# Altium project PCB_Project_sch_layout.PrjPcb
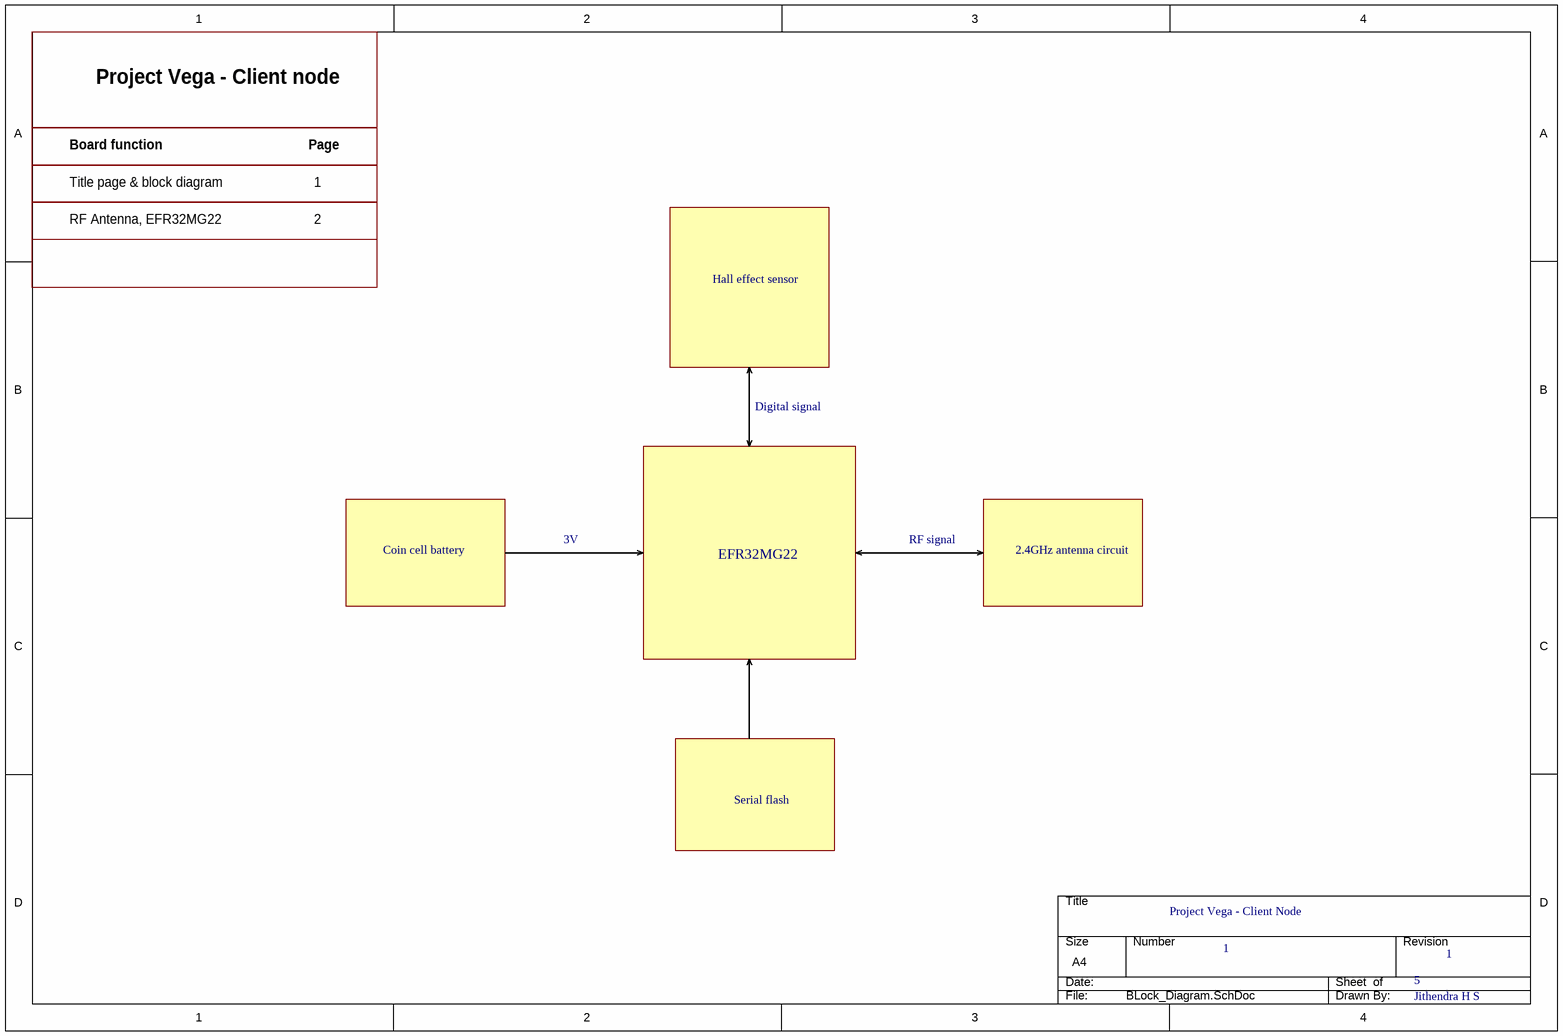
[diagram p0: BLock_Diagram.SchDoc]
5 sheets, 120 parts. Net scope: flat (ports and power ports of the same name join across sheets).
Sheets:
  BLock_Diagram.SchDoc
  Principal.SchDoc
  Power_Sheet.SchDoc
  Project_Vega_Sensors_Schematic.SchDoc
  Client_Node.SchDoc

## Sheet BLock_Diagram.SchDoc: Project Vega - Client Node
size A4; DrawnBy: Jithendra H S; Revision: 1; SheetNumber: 1; SheetTotal: 5

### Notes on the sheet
- Project Vega - Client node
- Board function
- Page
- Title page & block diagram
- RF Antenna, EFR32MG22
- 1
- 2
- Hall effect sensor
- Digital signal
- Coin cell battery
- 3V
- EFR32MG22
- RF signal
- 2.4GHz antenna circuit
- Serial flash

## Sheet Principal.SchDoc
size A4; SheetNumber: 1; SheetTotal: 5
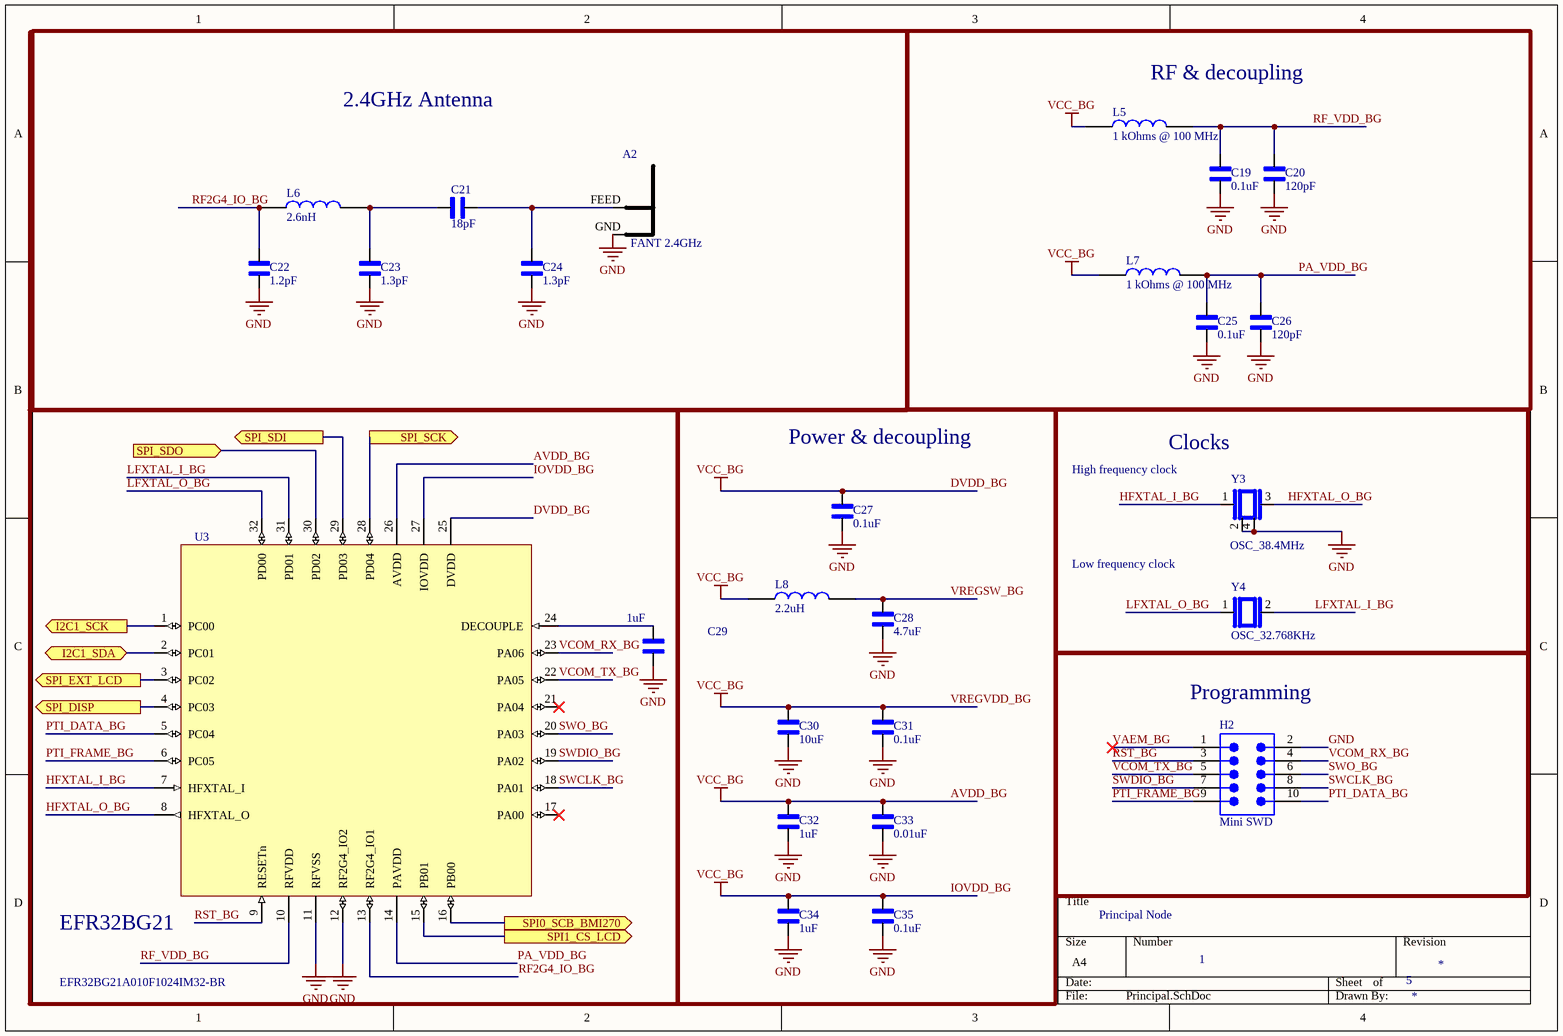
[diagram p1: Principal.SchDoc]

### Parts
A2  FANT 2.4GHz  [FANT_2P4]
C19  0.1uF  [CAPC1608X90]
C20  120pF  [CAPC1608X90]
C21  18pF  [CAPC1608X90]
C22  1.2pF  [CAPC1608X90]
C23  1.3pF  [CAPC1608X90]
C24  1.3pF  [CAPC1608X90]
C25  0.1uF  [CAPC1608X90]
C26  120pF  [CAPC1608X90]
C27  0.1uF  [CAPC1608X90]
C28  4.7uF  [CAPC1608X90]
C29  1uF  [CAPC1608X90]
C30  10uF  [CAPC1608X90]
C31  0.1uF  [CAPC1608X90]
C32  1uF  [CAPC1608X90]
C33  0.01uF  [CAPC1608X90]
C34  1uF  [CAPC1608X90]
C35  0.1uF  [CAPC1608X90]
H2  Mini SWD  [FTSH-105-01-XXX-DV-K]
L5  1 kOhms @ 100 MHz  [INDC1608X95N]
L6  2.6nH  [INDC1608X95N]
L7  1 kOhms @ 100 MHz  [INDC1608X95N]
L8  2.2uH  [INDC1608X95N]
U3  EFR32BG21A010F1024IM32-BR  [QFN32-EFR32xG2xIM32-BR]
Y3  OSC_38.4MHz  [OSC_38.4MHz]
Y4  OSC_32.768KHz  [OSC_32.768KHz]

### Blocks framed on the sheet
2.4GHz Antenna: A2 C21-C24 L6
RF & decoupling: C19 C20 C25 C26 L5 L7
EFR32BG21: C29 U3
Power & decoupling: C27 C28 C30-C35 L8
Clocks: Y3 Y4
Programming: H2

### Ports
I2C1_SCK (out, see Project_Vega_Sensors_Schematic[3A], Project_Vega_Sensors_Schematic[3C]), I2C1_SDA (bidir, see Project_Vega_Sensors_Schematic[3A], Project_Vega_Sensors_Schematic[3C]), SPI0_SCB_BMI270 (out, see Project_Vega_Sensors_Schematic[1A]), SPI1_CS_LCD (out, see Project_Vega_Sensors_Schematic[1C]), SPI_DISP (out, see Project_Vega_Sensors_Schematic[1C]), SPI_EXT_LCD (out, see Project_Vega_Sensors_Schematic[1C]), SPI_SCK (out, see Project_Vega_Sensors_Schematic[1A], Project_Vega_Sensors_Schematic[1C]), SPI_SDI (out, see Project_Vega_Sensors_Schematic[1A], Project_Vega_Sensors_Schematic[1C]), SPI_SDO (in, see Project_Vega_Sensors_Schematic[1A])

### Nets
AVDD_BG: C27.1 C30.1 C31.1 C32.1 C33.1 C34.1 C35.1 L5.1 L7.1 L8.1 U3.25(DVDD) U3.26(AVDD) U3.27(IOVDD)  [also labelled DVDD_BG, IOVDD_BG, VCC_BG, VREGVDD_BG]
GND: A2.GND C19.2 C20.2 C22.2 C23.2 C24.2 C25.2 C26.2 C27.2 C28.2 C29.2 C30.2 C31.2 C32.2 C33.2 C34.2 C35.2 H2.2 U3.11(RFVSS) U3.12(RF2G4_IO2) Y3.2 Y3.4
HFXTAL_I_BG: U3.7(HFXTAL_I) Y3.1
HFXTAL_O_BG: U3.8(HFXTAL_O) Y3.3
LFXTAL_I_BG: U3.31(PD01) Y4.2
LFXTAL_O_BG: U3.32(PD00) Y4.1
PA_VDD_BG: C25.1 C26.1 L7.2 U3.14(PAVDD)
PTI_DATA_BG: H2.10 U3.5(PC04)
PTI_FRAME_BG: H2.9 U3.6(PC05)
RF2G4_IO_BG: C22.1 L6.1 U3.13(RF2G4_IO1)
RF_VDD_BG: C19.1 C20.1 L5.2 U3.10(RFVDD)
RST_BG: H2.3 U3.9(RESETn)
SWCLK_BG: H2.8 U3.18(PA01)
SWDIO_BG: H2.7 U3.19(PA02)
SWO_BG: H2.6 U3.20(PA03)
VAEM_BG: H2.1
VCOM_RX_BG: H2.4 U3.23(PA06)
VCOM_TX_BG: H2.5 U3.22(PA05)
VREGSW_BG: C28.1 L8.2
NetA2_FEED: A2.FEED C21.2 C24.1
NetC21_1: C21.1 C23.1 L6.2
NetC29_1: C29.1 U3.24(DECOUPLE)
NetC?#6_2: U3.4(PC03) ; port SPI_DISP
NetP?_1: U3.28(PD04) ; port SPI_SCK
NetP?_2: U3.29(PD03) ; port SPI_SDI
NetP?_3: U3.15(PB01) ; port SPI1_CS_LCD
NetP?_4: U3.3(PC02) ; port SPI_EXT_LCD
NetR?#2_1: U3.2(PC01) ; port I2C1_SDA
NetR?#3_1: U3.1(PC00) ; port I2C1_SCK
NetU3_16: U3.16(PB00) ; port SPI0_SCB_BMI270
NetU3_30: U3.30(PD02) ; port SPI_SDO

Not connected (* = marked no-connect by the designer): U3 17(PA00)* 21(PA04)*

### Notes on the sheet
- (near Y3) High frequency clock
- Low frequency clock
- Principal Node

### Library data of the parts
A2 = FANT_2P4: Inverted F antenna
C19-C35 = CC0603KRX7R9BB104: 0.1 ÂµF Â±10% 50V Ceramic Capacitor X7R 0603 (1608 Metric); MF: Yageo
H2 = Debug Connector Mini SWD - 0.05": Mini SWD 0.05" Pitch Connector - 10 Pin SMT Box Header; Manufacturer: Adafruit Industries; Manufacturer Part Number: 4048
L5-L8 = LQM18DN100M70L: Inductor with Inductance 10uH Tol.+/-20% Package 0603 (1608); MF: Murata Electronics
U3 = EFR32BG21A010F1024IM32-BR: Blue Gecko, QFN32, 2.4G, 10dB, Bluetooth 5.1, 1024kB, 96kB(RAM), 20 GPIO; Manufacturer: Silicon Labs
Y3 = OSC_38.4MHz: 38.4 MHz ±10ppm Crystal 10pF 40 Ohms 4-SMD, No Lead; MF: {'manufacturer': u'Murata Electronics'}; MP: XRCGB38M400F2P00R0
Y4 = OSC_32.768KHz: Tuning Fork Crystal 32.768kHz in 1.2 x 2.0mm package; MF: Micro Crystal; MP: CM8V-T1A-32.768KHZ-7PF-20PPM-TA-QC

## Sheet Power_Sheet.SchDoc
size A4; SheetNumber: 2; SheetTotal: 5
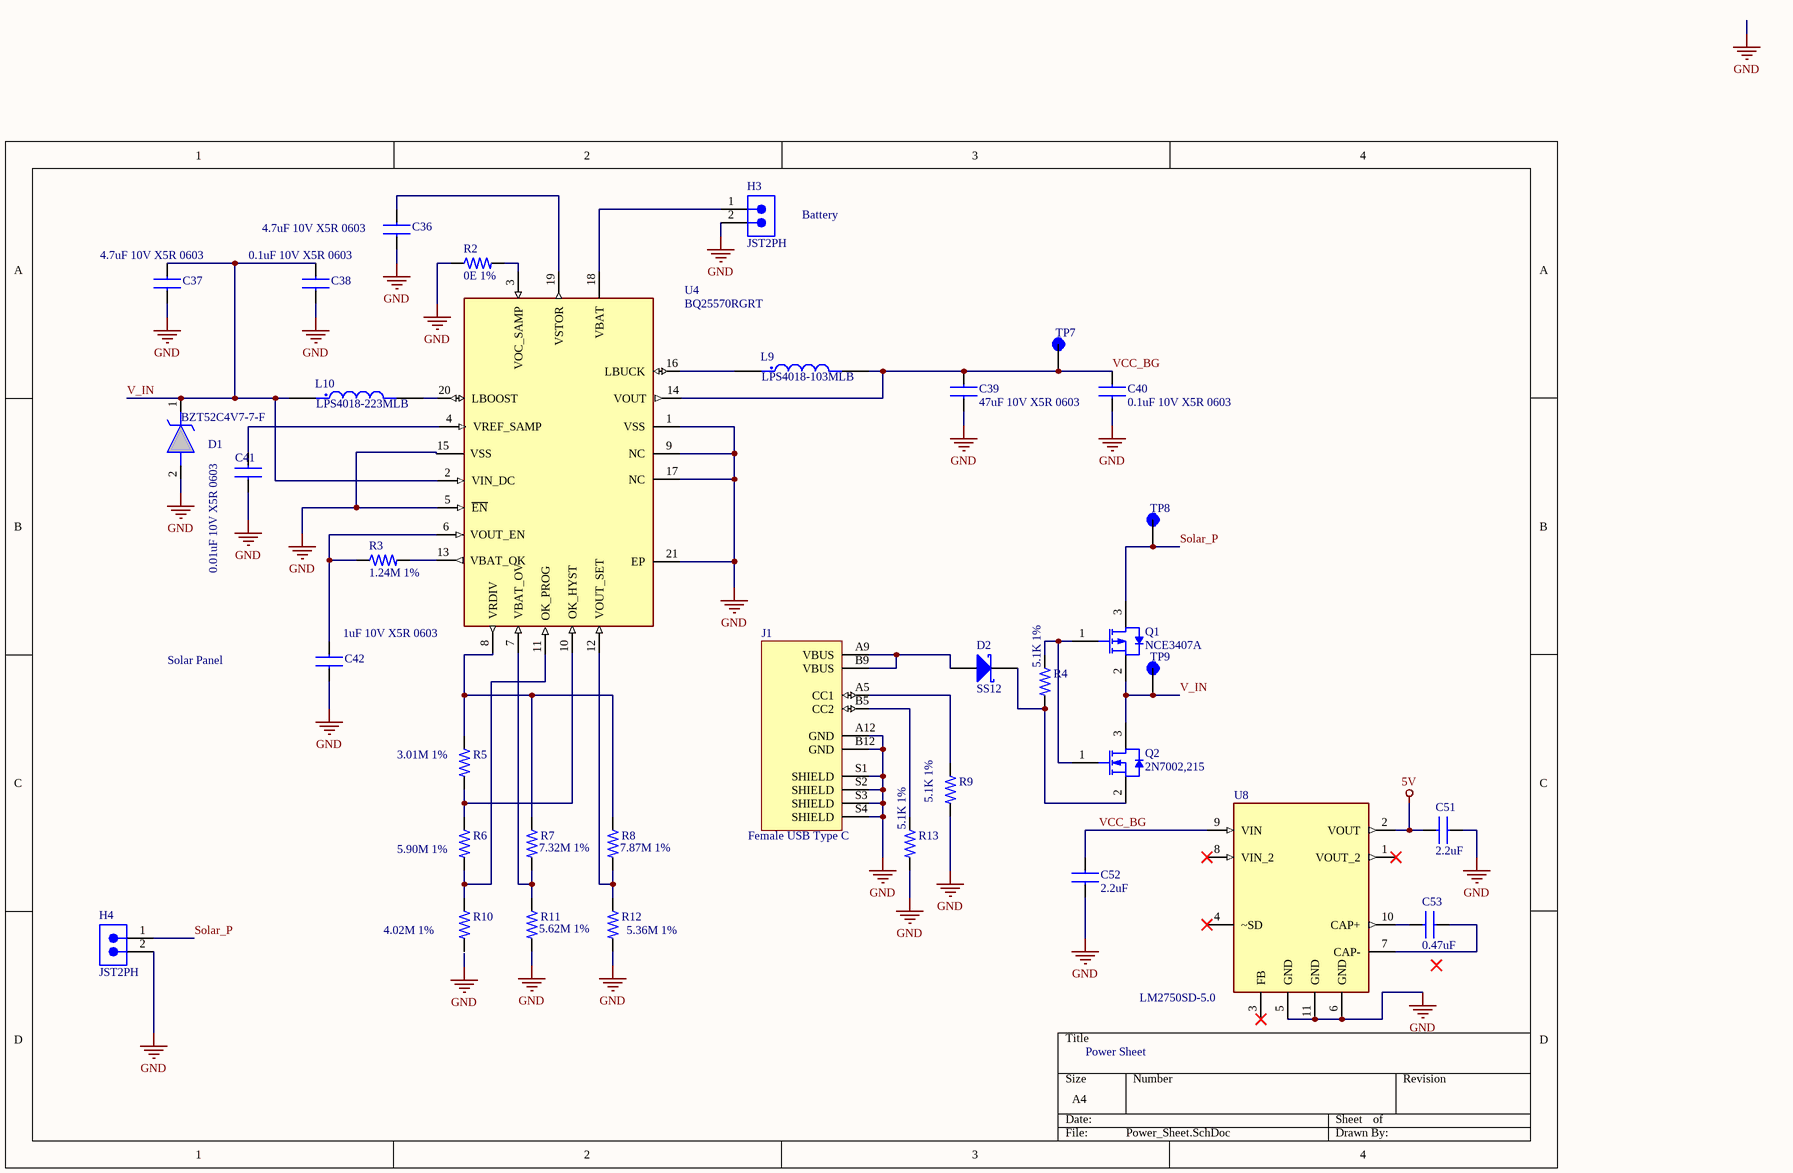
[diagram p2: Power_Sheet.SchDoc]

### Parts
C36  4.7uF 10V X5R 0603  [CAP_0603_1MM]
C37  4.7uF 10V X5R 0603  [CAP_0603_1MM]
C38  0.1uF 10V X5R 0603  [CAP_0603_1MM]
C39  47uF 10V X5R 0603  [CAP_0603_1MM]
C40  0.1uF 10V X5R 0603  [CAP_0603_1MM]
C41  0.01uF 10V X5R 0603  [CAP_0603_1MM]
C42  1uF 10V X5R 0603  [CAP_0603_1MM]
C51  2.2uF  [CAP_0603_1MM]
C52  2.2uF  [CAP_0603_1MM]
C53  0.47uF  [CAP_0603_1MM]
D1  BZT52C4V7-7-F  [SOD3716X145N]
D2  SS12  [FAIR-DO-214AC-2_V]
H3  JST2PH  [JST_B2B-PH-K-S(LF)(SN)]
H4  JST2PH  [JST_B2B-PH-K-S(LF)(SN)]
J1  Female USB Type C  [GCT_USB4125-GF-A_REVA2]
L9  LPS4018-103MLB  [IND_LPS4018-223MRC]
L10  LPS4018-223MLB  [IND_LPS4018-223MRC]
Q1  NCE3407A  [NCEP-SOT23-3_M]
Q2  2N7002,215  [NXP-SOT23-3_V]
R2  0E 1%  [RES_0603_1608X06]
R3  1.24M 1%  [RES_0603_1608X06]
R4  5.1K 1%  [RES_0603_1608X06]
R5  3.01M 1%  [RES_0603_1608X06]
R6  5.90M 1%  [RES_0603_1608X06]
R7  7.32M 1%  [RES_0603_1608X06]
R8  7.87M 1%  [RES_0603_1608X06]
R9  5.1K 1%  [RES_0603_1608X06]
R10  4.02M 1%  [RES_0603_1608X06]
R11  5.62M 1%  [RES_0603_1608X06]
R12  5.36M 1%  [RES_0603_1608X06]
R13  5.1K 1%  [RES_0603_1608X06]
TP7  Test_point  [TP]  (value not drawn)
TP8  Test_point  [TP]  (value not drawn)
TP9  Test_point  [TP]  (value not drawn)
U4  BQ25570RGRT  [QFN50P350X350X100-21N]
U8  LM2750SD-5.0  [LM2750_DFN300X300X80-11N]

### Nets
5V: C51.2 U8.2(VOUT)
GND: C36.1 C37.1 C38.1 C39.1 C40.1 C41.1 C42.1 C51.1 C52.1 D1.2(A) H3.2 H4.2 J1.A12(GND) J1.B12(GND) J1.S1(SHIELD) J1.S2(SHIELD) J1.S3(SHIELD) J1.S4(SHIELD) R2.1 R9.2 R11.2 R12.2 R13.2 U4.1(VSS) U4.5(~{EN}) U4.9(NC) U4.15(VSS) U4.17(NC) U4.21(EP) U8.5(GND) U8.6(GND) U8.11(GND)
Solar_P: H4.1 Q1.3(DRAIN) TP8.TP
V_IN: C37.2 C38.2 D1.1(K) L10.1 Q1.2(SOURCE) Q2.3(D) TP9.TP U4.2(VIN_DC)
VCC_BG: C39.2 C40.2 C52.2 L9.2 TP7.TP U4.14(VOUT) U8.9(VIN)
NetC36_2: C36.2 U4.19(VSTOR)
NetC41_2: C41.2 U4.4(VREF_SAMP)
NetC42_2: C42.2 R3.1 U4.6(VOUT_EN)
NetC53_1: C53.1 U8.7(CAP-)
NetC53_2: C53.2 U8.10(CAP+)
NetD2_1: D2.1(A) J1.A9(VBUS) J1.B9(VBUS)
NetD2_2: D2.2(K) Q2.2(S) R4.2
NetH3_1: H3.1 U4.18(VBAT)
NetJ1_A5: J1.A5(CC1) R9.1
NetJ1_B5: J1.B5(CC2) R13.1
NetL9_1: L9.1 U4.16(LBUCK)
NetL10_2: L10.2 U4.20(LBOOST)
NetQ1_1: Q1.1(GATE) Q2.1(G) R4.1
NetR2_2: R2.2 U4.3(VOC_SAMP)
NetR3_2: R3.2 U4.13(VBAT_OK)
NetR5_1: R5.1 R7.1 R8.1 U4.8(VRDIV)
NetR5_2: R5.2 R6.1 U4.10(OK_HYST)
NetR6_2: R6.2 R10.1 U4.11(OK_PROG)
NetR7_2: R7.2 R11.1 U4.7(VBAT_OV)
NetR8_2: R8.2 R12.1 U4.12(VOUT_SET)

Not connected (* = marked no-connect by the designer): R10 2; U8 1(VOUT_2)* 3(FB)* 4(~SD)* 8(VIN_2)*

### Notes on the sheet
- Battery
- Solar Panel
- Power Sheet

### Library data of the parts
C36-C42 C52 C53 = GRM188R61A226ME15D: CAP CER 22UF 10V X5R 0603; Manufacturer: Murata; Voltage Rating DC: 10 VDC; Tolerance: 20 %; Brand: Murata Electronics; Type: Voltage and Temperature Derating Recommended Product; Unit Weight: 0.000222 oz
C51 = GRM188R61A226ME15D: Manufacturer: Murata; Capacitance: 22 uF; Voltage Rating DC: 10 VDC; Dielectric: X5R; Tolerance: 20 %; Brand: Murata Electronics; Type: Voltage and Temperature Derating Recommended Product; Unit Weight: 0.000222 oz
D1 = BZT52C4V7-7-F: Diodes Inc BZT52C4V7-7-F Zener Diode, 4.7V 7% 500 mW SMT 2-Pin SOD-123; Manufacturer_Name: Diodes Incorporated; Geometry.Height: 1.45mm
D2 = CMP-004-00016-2: Schottky Rectifier, 20 V, 1 A, -65 to 125 degC, 2-Pin DO-214AC, RoHS, Tape and Reel; Manufacturer: Fairchild; Forward Voltage: 500mV; Peak Reverse Current: 200uA; Max Surge Current: 40A
H3 H4 = JST2PH: Connector Header Through Hole 2 position 0.079" (2.00mm); Manufacturer: JST; Manufacturer Part Number: B2B-PH-K-S
J1 = USB-C Power Connector: USB-C (USB TYPE-C) Receptacle Connector 24 (6+18 Dummy) Position Surface Mount, Right Angle; Through Hole; Manufacturer Part Number: USB4125-GF-A_REVA2
L9 L10 = LPS4018-223MRC: 22 µH Shielded Drum Core Inductor 650 mA 360mOhm Max Nonstandard; MF: Coilcraft
Q1 = CMP-013-00018-3: P-Channel Enhancement Mode Power MOSFET, 30 V, 4.3 A, - 55 to 150 degC, 3-Pin SOT23, RoHS, Tape and Reel; Manufacturer: NCE Power
Q2 = CMP-013-00011-4: N-channel Trench MOSFET, 60 V, 300 mA, -65 to 150 degC, 3-Pin SOT-23 (TO-236AB), RoHS, Tape and Reel; Manufacturer: NXP Semiconductors; Elements: 1; Power: 830mW; Max Dual Supply Voltage: 60V; Rds On Max: 5Ohm; Package Version: Feb-16; Nominal Vgs: 2V; Input Capacitance: 50pF
R2 R3 R5-R12 = RC0603FR-07316KL: SMD Chip Resistor, 316 kOhm, ± 1%, 100 mW, 0603 [1608 Metric], Thick Film, General Purpose; Manufacturer: Yageo; Value: 316kR; Power Rating: 100mW; Voltage Rating: 50V; Temperature Coefficient: 100ppm/°C
R4 R13 = RC0603FR-07316KL: SMD Chip Resistor, 5.1KOhm, ± 1%, 100 mW, 0603 [1608 Metric], Thick Film, General Purpose; Manufacturer: Yageo; Value: 316kR; Power Rating: 100mW; Voltage Rating: 50V; Temperature Coefficient: 100ppm/°C
TP7-TP9 = Test_point: SMT Test Point- Mininature-1000 pc Reels; MP: 5019; MF: Keystone Electronics
U4 = BQ25570RGRT: Ultra Low power Harvester power Management IC with boost charger, and Nanopower Buck Converter 20-VQFN -40 to 125; MF: Texas Instruments
U8 = LM2750SD-5.0: IC CONV REG SW CAP 5V; MP: LM2750SD-5-0

## Sheet Project_Vega_Sensors_Schematic.SchDoc: Principal Node_Sensor Schematic
size A; Date: 10/08/2024; Author: Prudhvi Kondapalli; CompanyName: CU Boulder; Engineer: Prudhvi Kondapalli; DocumentNumber: 1; Revision: 1; SheetNumber: 5; SheetTotal: 5
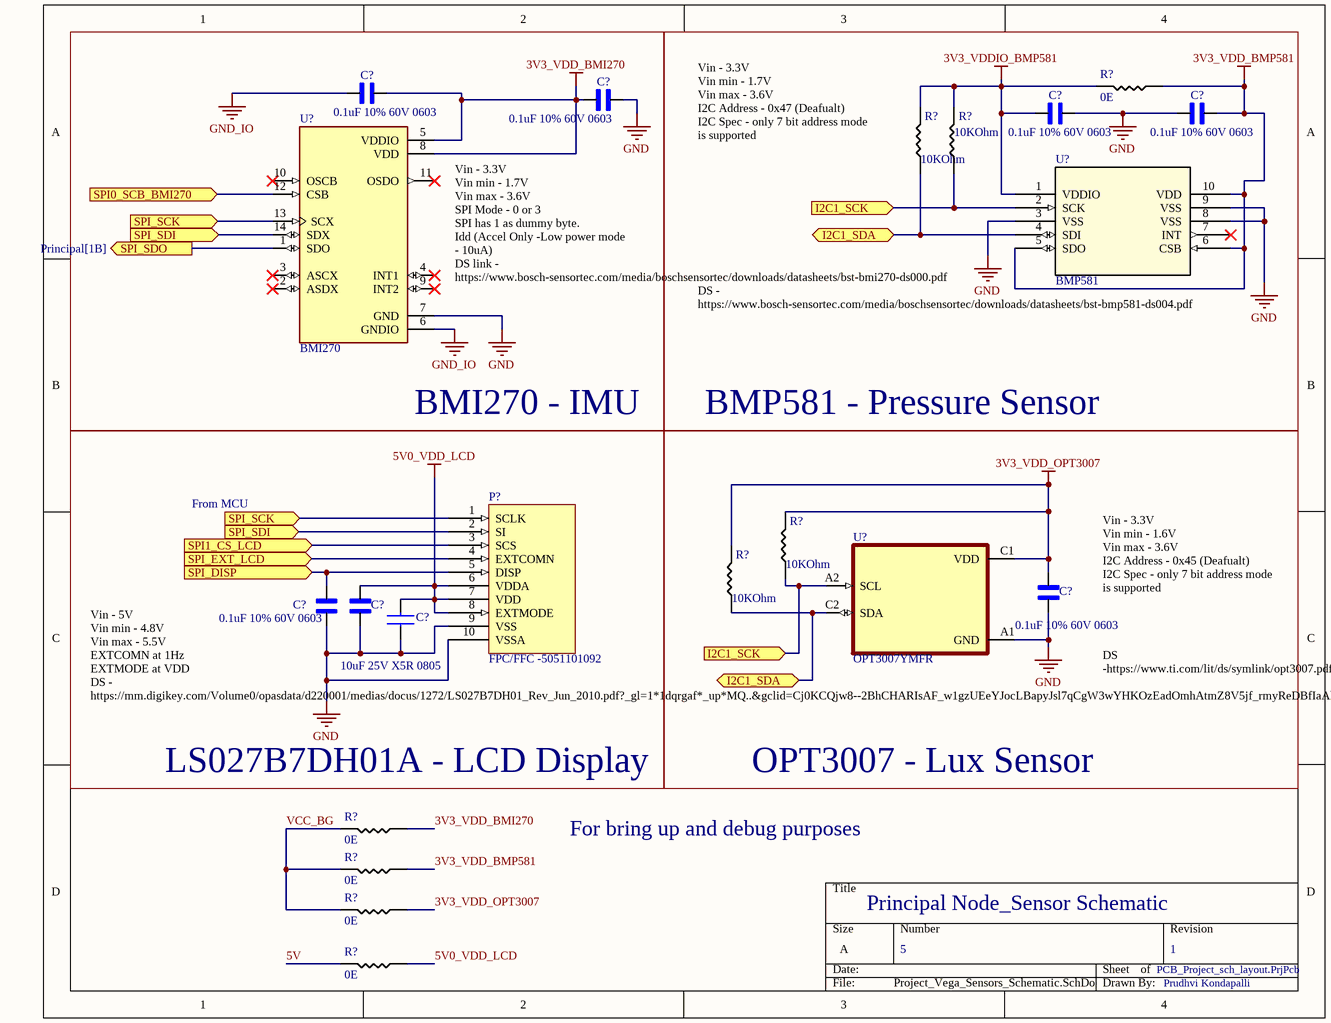
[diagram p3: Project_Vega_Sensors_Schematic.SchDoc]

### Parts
(Parts that share a designator on the sheet are numbered #1, #2 ... from top to bottom, then left to right.)
C?#1  0.1uF 10% 60V 0603  [CAPC1608X90]
C?#2  0.1uF 10% 60V 0603  [CAPC1608X90]
C?#3  0.1uF 10% 60V 0603  [CAPC1608X90]
C?#4  0.1uF 10% 60V 0603  [CAPC1608X90]
C?#5  0.1uF 10% 60V 0603  [CAPC1608X90]
C?#6  0.1uF 10% 60V 0603  [CAPC1608X90]
C?#7  0.1uF 10% 60V 0603  [CAPC1608X90]  (value not drawn)
C?#8  10uF 25V X5R 0805  [CAP_0805_2mmX1.25mm]
P?  FPC/FFC -5051101092  [CON_5051101092_MOL]
R?#1  value 0E  [1206_Passive_Resitor]  (hidden comment: 10k)
R?#2  value 10KOhm  [1206_Passive_Resitor]  (hidden comment: 10k)
R?#3  value 10KOhm  [1206_Passive_Resitor]  (hidden comment: 10k)
R?#4  value 10KOhm  [1206_Passive_Resitor]  (hidden comment: 10k)
R?#5  value 10KOhm  [1206_Passive_Resitor]  (hidden comment: 10k)
R?#6  value 0E  [1206_Passive_Resitor]  (hidden comment: 10k)
R?#7  value 0E  [1206_Passive_Resitor]  (hidden comment: 10k)
R?#8  value 0E  [1206_Passive_Resitor]  (hidden comment: 10k)
R?#9  value 0E  [1206_Passive_Resitor]  (hidden comment: 10k)
U?#1  BMP581  [QFN10_BMP581_BOS-M]
U?#2  BMI270  [XDCR_BMI270]
U?#3  OPT3007YMFR  [BGA6N60X35P2X3_85X94X22N]

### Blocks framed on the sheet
BMI270 - IMU: C?#1 C?#2 U?#2
BMP581 - Pressure Sensor: C?#3 C?#4 R?#1-R?#3 U?#1

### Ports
I2C1_SCK (in, see Principal[1C], Project_Vega_Sensors_Schematic[3A]), I2C1_SCK (in, see Principal[1C], Project_Vega_Sensors_Schematic[3C]), I2C1_SDA (bidir, see Principal[1C], Project_Vega_Sensors_Schematic[3A]), I2C1_SDA (bidir, see Principal[1C], Project_Vega_Sensors_Schematic[3C]), SPI0_SCB_BMI270 (in, see Principal[2D]), SPI1_CS_LCD (in, see Principal[2D]), SPI_DISP (in, see Principal[1C]), SPI_EXT_LCD (in, see Principal[1C]), SPI_SCK (in, see Principal[1B], Project_Vega_Sensors_Schematic[1A]), SPI_SCK (in, see Principal[1B], Project_Vega_Sensors_Schematic[1C]), SPI_SDI (in, see Principal[1B], Project_Vega_Sensors_Schematic[1A]), SPI_SDI (in, see Principal[1B], Project_Vega_Sensors_Schematic[1C]), SPI_SDO (out, see Principal[1B])

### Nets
3V3_VDD_BMI270: C?#1.2 C?#2.1 R?#6.1 U?#2.5(VDDIO) U?#2.8(VDD)
3V3_VDD_BMP581: C?#4.2 R?#1.1 R?#7.1 U?#1.5(SDO) U?#1.6(CSB) U?#1.10(VDD)
3V3_VDD_OPT3007: C?#5.2 R?#4.2 R?#5.2 R?#8.1 U?#3.C1(VDD)
3V3_VDDIO_BMP581: C?#3.1 R?#1.2 R?#2.2 R?#3.2 U?#1.1(VDDIO)
5V0_VDD_LCD: C?#7.2 C?#8.1 P?.6(VDDA) P?.7(VDD) P?.8(EXTMODE) R?#9.1
GND: C?#2.2 C?#3.2 C?#4.1 C?#5.1 C?#6.1 C?#7.1 C?#8.2 P?.9(VSS) P?.10(VSSA) U?#1.3(VSS) U?#1.8(VSS) U?#1.9(VSS) U?#2.7(GND) U?#3.A1(GND)
GND_IO: C?#1.1 U?#2.6(GNDIO)
5V: R?#9.2
VCC_BG: R?#6.2 R?#7.2 R?#8.2
NetC?#6_2: C?#6.2 P?.5(DISP) ; port SPI_DISP
NetP?_1: P?.1(SCLK) U?#2.13(SCX) ; port SPI_SCK
NetP?_2: P?.2(SI) U?#2.14(SDX) ; port SPI_SDI
NetP?_3: P?.3(SCS) ; port SPI1_CS_LCD
NetP?_4: P?.4(EXTCOMN) ; port SPI_EXT_LCD
NetR?#2_1: R?#2.1 R?#5.1 U?#1.4(SDI) U?#3.C2(SDA) ; port I2C1_SDA
NetR?#3_1: R?#3.1 R?#4.1 U?#1.2(SCK) U?#3.A2(SCL) ; port I2C1_SCK
NetU3_16: U?#2.12(CSB) ; port SPI0_SCB_BMI270
NetU3_30: U?#2.1(SDO) ; port SPI_SDO

Not connected (* = marked no-connect by the designer): U?#1 7(INT)*; U?#2 2(ASDX)* 3(ASCX)* 4(INT1)* 9(INT2)* 10(OSCB)* 11(OSDO)*

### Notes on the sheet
- (near R?#2) Vin - 3.3V
  Vin min - 1.7V
  Vin max - 3.6V
  I2C Address - 0x47 (Deafualt)
  I2C Spec - only 7 bit address mode is supported
- Vin - 3.3V
  Vin min - 1.7V
  Vin max - 3.6V
  SPI Mode - 0 or 3
  SPI has 1 as dummy byte.
  Idd (Accel Only -Low power mode - 10uA)
  DS link - https://www.bosch-sensortec.com/media/boschsensortec/downloads/datasheets/bst-bmi270-ds000.pdf
- DS - https://www.bosch-sensortec.com/media/boschsensortec/downloads/datasheets/bst-bmp581-ds004.pdf
- From MCU
- Vin - 3.3V
  Vin min - 1.6V
  Vin max - 3.6V
  I2C Address - 0x45 (Deafualt)
  I2C Spec - only 7 bit address mode is supported
- DS -https://www.ti.com/lit/ds/symlink/opt3007.pdf?HQS=dis-dk-null-digikeymode-dsf-pf-null-wwe&ts=1728281957104&ref_url=https%253A%252F%252Fwww.ti.com%252Fgeneral%252Fdocs%252Fsuppproductinfo.tsp%253FdistId%253D10%2526gotoUrl%253Dhttps%253A%252F%252Fwww.ti.com%252Flit%252Fgpn%252Fopt3007
- Vin - 5V
  Vin min - 4.8V
  Vin max - 5.5V
  EXTCOMN at 1Hz
  EXTMODE at VDD
  DS - https://mm.digikey.com/Volume0/opasdata/d220001/medias/docus/1272/LS027B7DH01_Rev_Jun_2010.pdf?_gl=1*1dqrgaf*_up*MQ..&gclid=Cj0KCQjw8--2BhCHARIsAF_w1gzUEeYJocLBapyJsl7qCgW3wYHKOzEadOmhAtmZ8V5jf_rmyReDBfIaAkmEEALw_wcB
- (near R?#6) LS027B7DH01A - LCD Display
- OPT3007 - Lux Sensor
- For bring up and debug purposes

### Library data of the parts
C?#1-C?#7 = CC0603KRX7R9BB104: as C19 on sheet Principal
C?#8 = GRM21BR61E106KA73K: Multilayer Ceramic Capacitor, 10 uF, 25 V, +/- 10%, X5R, 0805 [2012 Metric]; Manufacturer: Murata
P? = 5051101092: 10 Position FFC, FPC Connector Contacts, Bottom 0.020" (0.50mm) Surface Mount, Right Angle
R?#1-R?#9 = R_10KOhm_1206: 10 kOhms ±5% 0.25W, 1/4W Chip Resistor 1206 (3216 Metric) Automotive AEC-Q200 Thick Film; MFR Part #: RMCF1206FT10K0
U?#1 = BMP581: No Description Available; Mfr_Name: Bosch Sensortec
U?#2 = BMI270: Accelerometer, Gyroscope, 6 Axis Sensor IÂ²C, SPI Output; MF: Bosch Sensortec
U?#3 = OPT3007YMFR: Ultra-thin ambient light sensor (ALS) with fixed I2C address 6-PICOSTAR -40 to 85; MF: Texas Instruments

## Sheet Client_Node.SchDoc: Project Vega - Client Node
size A4; DrawnBy: Jithendra H S; Revision: 1; SheetNumber: 4; SheetTotal: 5
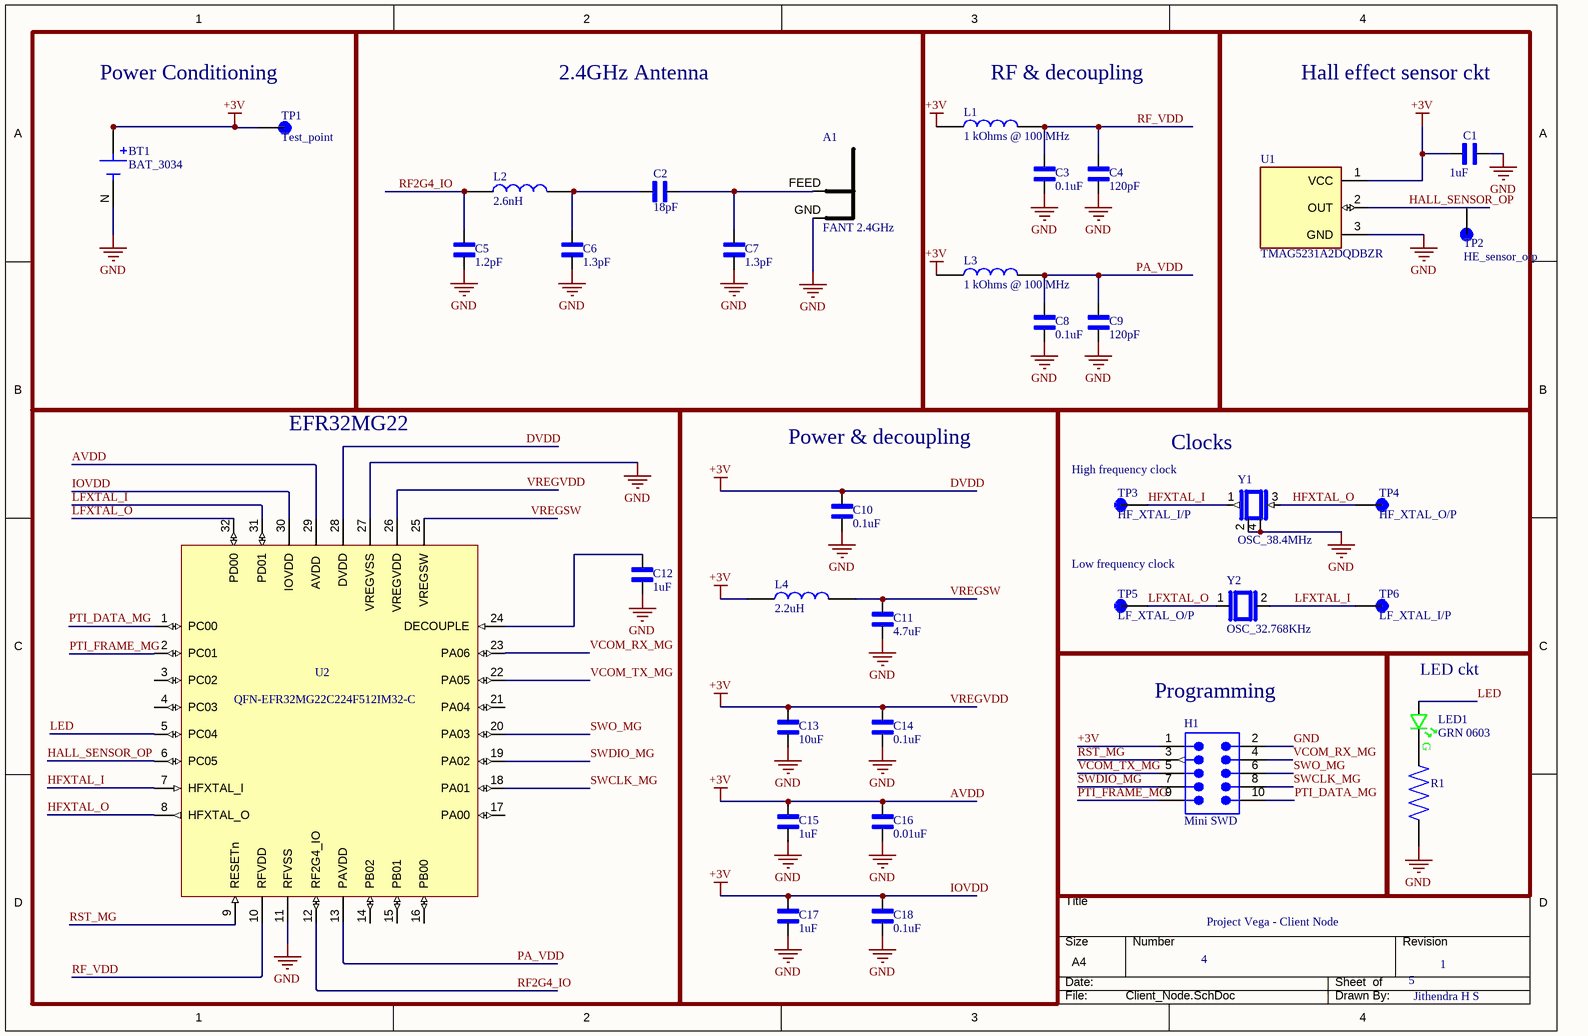
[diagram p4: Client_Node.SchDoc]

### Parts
A1  FANT 2.4GHz  [FANT_2P4]
BT1  BAT_3034  [BAT_3034]
C1  1uF  [CAPC1608X90]
C2  18pF  [CAPC1608X90]
C3  0.1uF  [CAPC1608X90]
C4  120pF  [CAPC1608X90]
C5  1.2pF  [CAPC1608X90]
C6  1.3pF  [CAPC1608X90]
C7  1.3pF  [CAPC1608X90]
C8  0.1uF  [CAPC1608X90]
C9  120pF  [CAPC1608X90]
C10  0.1uF  [CAPC1608X90]
C11  4.7uF  [CAPC1608X90]
C12  1uF  [CAPC1608X90]
C13  10uF  [CAPC1608X90]
C14  0.1uF  [CAPC1608X90]
C15  1uF  [CAPC1608X90]
C16  0.01uF  [CAPC1608X90]
C17  1uF  [CAPC1608X90]
C18  0.1uF  [CAPC1608X90]
H1  Mini SWD  [FTSH-105-01-XXX-DV-K]
L1  1 kOhms @ 100 MHz  [INDC1608X95N]
L2  2.6nH  [INDC1608X95N]
L3  1 kOhms @ 100 MHz  [INDC1608X95N]
L4  2.2uH  [INDC1608X95N]
LED1  GRN 0603  [LED_0603_GRN_WL-SMCW]
R1  RES_0603  [RES_0603]  (value not drawn)
TP1  Test_point  [TP]
TP2  HE_sensor_o/p  [TP]
TP3  HF_XTAL_I/P  [TP]
TP4  HF_XTAL_O/P  [TP]
TP5  LF_XTAL_O/P  [TP]
TP6  LF_XTAL_I/P  [TP]
U1  TMAG5231A2DQDBZR  [SOT95P237X112-3N]
U2  QFN-EFR32MG22C224F512IM32-C  [QFN32-EFR32xG2xIM32-BR]
Y1  OSC_38.4MHz  [OSC_38.4MHz]
Y2  OSC_32.768KHz  [OSC_32.768KHz]

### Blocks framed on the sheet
Power Conditioning: BT1 TP1
2.4GHz Antenna: A1 C2 C5-C7 L2
RF & decoupling: C3 C4 C8 C9 L1 L3
Hall effect sensor ckt: C1 TP2 U1
EFR32MG22: C12 U2
Power & decoupling: C10 C11 C13-C18 L4
Clocks: TP3-TP6 Y1 Y2
Programming: H1
LED ckt: LED1 R1

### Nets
+3V: BT1.P1(POS) BT1.P2(POS) C1.2 C10.1 C13.1 C14.1 C15.1 C16.1 C17.1 C18.1 H1.1 L1.1 L3.1 L4.1 TP1.TP U1.1(VCC) U2.26(VREGVDD) U2.28(DVDD) U2.29(AVDD) U2.30(IOVDD)  [also labelled AVDD, DVDD, IOVDD, VREGVDD]
GND: A1.GND BT1.N(NEG) C1.1 C3.2 C4.2 C5.2 C6.2 C7.2 C8.2 C9.2 C10.2 C11.2 C12.2 C13.2 C14.2 C15.2 C16.2 C17.2 C18.2 H1.2 R1.2 U1.3(GND) U2.11(RFVSS) U2.27(VREGVSS) Y1.2 Y1.4
HALL_SENSOR_OP: TP2.TP U1.2(OUT) U2.6(PC05)
HFXTAL_I: TP3.TP U2.7(HFXTAL_I) Y1.1
HFXTAL_O: TP4.TP U2.8(HFXTAL_O) Y1.3
LED: LED1.A U2.5(PC04)
LFXTAL_I: TP6.TP U2.31(PD01) Y2.2
LFXTAL_O: TP5.TP U2.32(PD00) Y2.1
PA_VDD: C8.1 C9.1 L3.2 U2.13(PAVDD)
PTI_DATA_MG: H1.10 U2.1(PC00)
PTI_FRAME_MG: H1.9 U2.2(PC01)
RF2G4_IO: C5.1 L2.1 U2.12(RF2G4_IO)
RF_VDD: C3.1 C4.1 L1.2 U2.10(RFVDD)
RST_MG: H1.3 U2.9(RESETn)
SWCLK_MG: H1.8 U2.18(PA01)
SWDIO_MG: H1.7 U2.19(PA02)
SWO_MG: H1.6 U2.20(PA03)
VCOM_RX_MG: H1.4 U2.23(PA06)
VCOM_TX_MG: H1.5 U2.22(PA05)
VREGSW: C11.1 L4.2 U2.25(VREGSW)
NetA1_FEED: A1.FEED C2.2 C7.1
NetC2_1: C2.1 C6.1 L2.2
NetC12_1: C12.1 U2.24(DECOUPLE)

Not connected (* = marked no-connect by the designer): LED1 C; R1 1; U2 3(PC02) 4(PC03) 14(PB02) 15(PB01) 16(PB00) 17(PA00) 21(PA04)

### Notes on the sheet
- (near TP3) High frequency clock
- Low frequency clock

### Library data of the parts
A1 = FANT_2P4: Inverted F antenna
BT1 = BAT_3034: SMT Holder for 20mm Cell-Tin Nickel Plate; MP: 3034; MF: Keystone Electronics Corp.
C1-C18 = CC0603KRX7R9BB104: as C19 on sheet Principal
H1 = Debug Connector Mini SWD - 0.05": as H2 on sheet Principal
L1-L4 = LQM18DN100M70L: as L5 on sheet Principal
LED1 = LED_green: LED, 0603, GREEN, 430MCD, 520NM; Manufacturer: Wurth Electronics; Manufacturer Part Number: 150060GS75000; Dynamic Catalog: 0603 Rectangle with Flat Top Chip LEDs; 3D Model: SMCW_0603.igs / SMCW_0603.stp / SMCW_0603.wrl; Wavelength - Peak: 515nm; Voltage - Forward (Vf) (Typ): 3.2V; Current - Test: 20mA; Viewing Angle: 140°; Lens Type: Clear; Lens Style/Size: Rectangle with Flat Top, 1.1mm x 0.7mm; Other Names: 732-4971-2
R1 = RES_0603: Thick film general purpose resistor 0603; MP: RC0603JR-070RL
TP1-TP6 = Test_point: as TP7 on sheet Power_Sheet
U1 = TMAG5231A2DQDBZR: SOT-23-3-Digital Switch Omnipolar Switch Push-Pull Hall Effect; MF: {'manufacturer': u'Texas Instruments'}
U2 = EFR32MG22C224F512IM32-C: IC RF TxRx + MCU WiFi Bluetooth v5.2, Zigbee® 2.4GHz 32-VFQFN Exposed Pad
Y1 = OSC_38.4MHz: as Y3 on sheet Principal
Y2 = OSC_32.768KHz: as Y4 on sheet Principal

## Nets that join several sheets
GND: Principal (22 pins), Power_Sheet (32 pins), Project_Vega_Sensors_Schematic (14 pins), Client_Node (26 pins)
NetC?#6_2: Principal (U3.4), Project_Vega_Sensors_Schematic (C?#6.2 P?.5)
NetP?_1: Principal (U3.28), Project_Vega_Sensors_Schematic (P?.1 U?#2.13)
NetP?_2: Principal (U3.29), Project_Vega_Sensors_Schematic (P?.2 U?#2.14)
NetP?_3: Principal (U3.15), Project_Vega_Sensors_Schematic (P?.3)
NetP?_4: Principal (U3.3), Project_Vega_Sensors_Schematic (P?.4)
NetR?#2_1: Principal (U3.2), Project_Vega_Sensors_Schematic (R?#2.1 R?#5.1 U?#1.4 U?#3.C2)
NetR?#3_1: Principal (U3.1), Project_Vega_Sensors_Schematic (R?#3.1 R?#4.1 U?#1.2 U?#3.A2)
NetU3_16: Principal (U3.16), Project_Vega_Sensors_Schematic (U?#2.12)
NetU3_30: Principal (U3.30), Project_Vega_Sensors_Schematic (U?#2.1)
